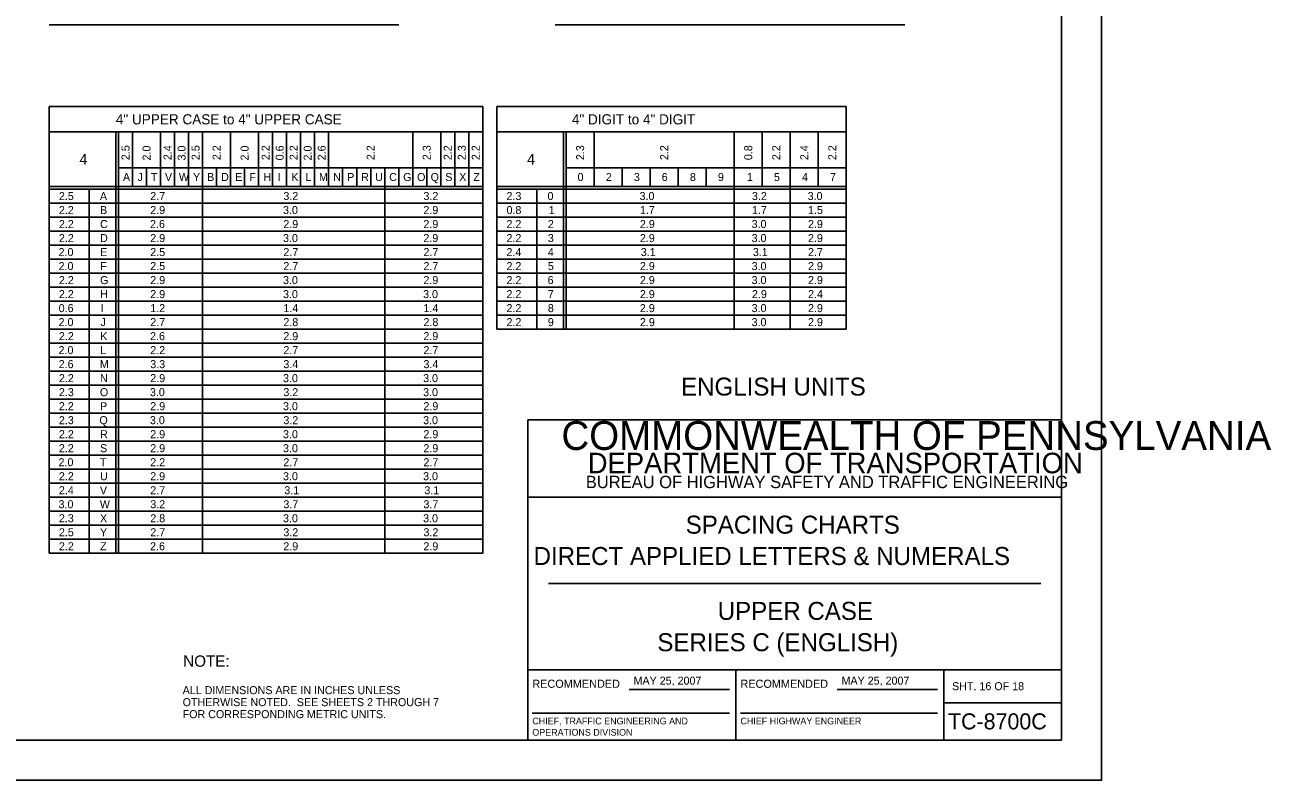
# Model space of a CAD drawing. Extents: x 637580 to 641849, y 297270 to 299646.
# Drawn here: x 640540.8 to 641007.9, y 297269.6 to 297552.6 of the extents above; entities that cross this region are included whole.
import ezdxf

# ---------------------------------------------------------------- set-up
doc = ezdxf.new("R2010")
doc.units = 0
for name, color, linetype in [('1', 7, 'Continuous'), ('2', 7, 'Continuous'), ('XCS-GRID-HVGL', 7, 'Continuous')]:
    doc.layers.add(name, color=color, linetype=linetype)

msp = doc.modelspace()

# ---------------------------------------------------------------- linework, layer by layer
at = {"layer": '1'}
for p, q in [((640929.31, 297284.63), (640929.31, 297848.63)), ((640729.31, 297284.63), (640729.31, 297404.63)), ((640729.31, 297404.63), (640929.31, 297404.63)), ((640929.31, 297375.63), (640729.31, 297375.63)), ((640737.06, 297343.31), (640921.56, 297343.31)), ((640729.31, 297311), (640929.31, 297311)), ((640807.31, 297311), (640807.31, 297284.63)), ((640885.19, 297284.63), (640885.19, 297311)), ((640767.24, 297303.57), (640804.87, 297303.57)), ((640845.24, 297303.57), (640882.87, 297303.57)), ((640885.19, 297298.63), (640929.31, 297298.63)), ((640730.99, 297294.68), (640804.87, 297294.68)), ((640808.99, 297294.68), (640882.87, 297294.68)), ((640929.31, 297284.63), (640143.31, 297284.63)), ((640143.31, 297284.63), (640729.31, 297284.63))]:
    msp.add_line(p, q, dxfattribs=at)
at = {"layer": '2'}
for p, q in [((640549.91, 297552.63), (640680.91, 297552.63)), ((640739.61, 297552.63), (640870.61, 297552.63)), ((640712.41, 297522), (640549.91, 297522)), ((640549.91, 297522), (640549.91, 297354.63)), ((640712.41, 297522), (640712.41, 297354.63)), ((640848.66, 297522), (640717.66, 297522)), ((640717.66, 297522), (640717.66, 297438.63)), ((640848.66, 297438.63), (640848.66, 297522)), ((640549.91, 297512.5), (640712.41, 297512.5)), ((640574.91, 297512.5), (640574.91, 297354.63)), ((640575.91, 297512.5), (640575.91, 297354.63)), ((640581.16, 297512.5), (640581.16, 297492.13)), ((640591.66, 297512.5), (640591.66, 297492.13)), ((640596.91, 297512.5), (640596.91, 297492.13)), ((640602.16, 297512.5), (640602.16, 297492.13)), ((640607.41, 297512.5), (640607.41, 297354.63)), ((640617.91, 297512.5), (640617.91, 297492.13)), ((640628.41, 297512.5), (640628.41, 297492.13)), ((640633.66, 297512.5), (640633.66, 297492.13)), ((640638.91, 297512.5), (640638.91, 297492.13)), ((640644.16, 297512.5), (640644.16, 297492.13)), ((640649.41, 297512.5), (640649.41, 297492.13)), ((640654.66, 297512.5), (640654.66, 297492.13)), ((640686.16, 297512.5), (640686.16, 297492.13)), ((640696.66, 297512.5), (640696.66, 297492.13)), ((640701.91, 297512.5), (640701.91, 297492.13)), ((640707.16, 297512.5), (640707.16, 297492.13)), ((640717.66, 297512.5), (640848.66, 297512.5)), ((640742.66, 297512.5), (640742.66, 297438.63)), ((640743.66, 297512.5), (640743.66, 297438.63)), ((640754.16, 297512.5), (640754.16, 297492.13)), ((640806.66, 297512.5), (640806.66, 297438.63)), ((640817.16, 297512.5), (640817.16, 297492.13)), ((640827.66, 297512.5), (640827.66, 297438.63)), ((640838.16, 297512.5), (640838.16, 297492.13)), ((640575.91, 297499.13), (640712.41, 297499.13)), ((640586.41, 297499.13), (640586.41, 297492.13)), ((640612.66, 297499.13), (640612.66, 297492.13)), ((640623.16, 297499.13), (640623.16, 297492.13)), ((640659.91, 297499.13), (640659.91, 297492.13)), ((640665.16, 297499.13), (640665.16, 297492.13)), ((640670.41, 297499.13), (640670.41, 297492.13)), ((640670.41, 297499.13), (640670.41, 297492.13)), ((640675.66, 297499.13), (640675.66, 297354.63)), ((640680.91, 297499.13), (640680.91, 297492.13)), ((640691.41, 297499.13), (640691.41, 297492.13)), ((640743.66, 297499.13), (640848.66, 297499.13)), ((640764.66, 297499.13), (640764.66, 297492.13)), ((640775.16, 297499.13), (640775.16, 297492.13)), ((640785.66, 297499.13), (640785.66, 297492.13)), ((640796.16, 297499.13), (640796.16, 297492.13)), ((640712.41, 297492.13), (640549.91, 297492.13)), ((640848.66, 297492.13), (640717.66, 297492.13)), ((640712.41, 297491.13), (640549.91, 297491.13)), ((640564.91, 297491.13), (640564.91, 297354.63)), ((640848.66, 297491.13), (640717.66, 297491.13)), ((640732.66, 297491.13), (640732.66, 297438.63)), ((640712.41, 297485.88), (640549.91, 297485.88)), ((640848.66, 297485.88), (640717.66, 297485.88)), ((640712.41, 297480.63), (640549.91, 297480.63)), ((640848.66, 297480.63), (640717.66, 297480.63)), ((640712.41, 297475.38), (640549.91, 297475.38)), ((640848.66, 297475.38), (640717.66, 297475.38)), ((640712.41, 297470.13), (640549.91, 297470.13)), ((640848.66, 297470.13), (640717.66, 297470.13)), ((640712.41, 297464.88), (640549.91, 297464.88)), ((640848.66, 297464.88), (640717.66, 297464.88)), ((640712.41, 297459.63), (640549.91, 297459.63)), ((640848.66, 297459.63), (640717.66, 297459.63)), ((640712.41, 297454.38), (640549.91, 297454.38)), ((640848.66, 297454.38), (640717.66, 297454.38)), ((640712.41, 297449.13), (640549.91, 297449.13)), ((640848.66, 297449.13), (640717.66, 297449.13)), ((640712.41, 297443.88), (640549.91, 297443.88)), ((640848.66, 297443.88), (640717.66, 297443.88)), ((640712.41, 297438.63), (640549.91, 297438.63)), ((640717.66, 297438.63), (640848.66, 297438.63)), ((640712.41, 297433.38), (640549.91, 297433.38)), ((640712.41, 297428.13), (640549.91, 297428.13)), ((640712.41, 297422.88), (640549.91, 297422.88)), ((640712.41, 297417.63), (640549.91, 297417.63)), ((640712.41, 297412.38), (640549.91, 297412.38)), ((640712.41, 297407.13), (640549.91, 297407.13)), ((640712.41, 297401.88), (640549.91, 297401.88)), ((640712.41, 297396.63), (640549.91, 297396.63)), ((640712.41, 297391.38), (640549.91, 297391.38)), ((640712.41, 297386.13), (640549.91, 297386.13)), ((640712.41, 297380.88), (640549.91, 297380.88)), ((640712.41, 297375.63), (640549.91, 297375.63)), ((640712.41, 297370.38), (640549.91, 297370.38)), ((640712.41, 297365.13), (640549.91, 297365.13)), ((640712.41, 297359.88), (640549.91, 297359.88)), ((640549.91, 297354.63), (640549.91, 297354.63)), ((640549.91, 297354.63), (640712.41, 297354.63))]:
    msp.add_line(p, q, dxfattribs=at)
at = {"layer": 'XCS-GRID-HVGL'}
msp.add_lwpolyline([(640103.31, 297863.63), (640944.31, 297863.63), (640944.31, 297269.63), (640103.31, 297269.63)], close=True, dxfattribs=at)

# ---------------------------------------------------------------- texts
at = {"layer": '1'}
for s, height, p in [('COMMONWEALTH OF PENNSYLVANIA', 10.7828, (640741.9, 297393.36)), ('DEPARTMENT OF TRANSPORTATION', 7.6837, (640751.76, 297384.61)), ('BUREAU OF HIGHWAY SAFETY AND TRAFFIC ENGINEERING', 4.6253, (640751.04, 297379.04)), ('SPACING CHARTS', 6.75, (640788.47, 297361.97)), ('DIRECT APPLIED LETTERS & NUMERALS', 6.75, (640731.47, 297350.22)), ('UPPER CASE', 6.75, (640800.47, 297329.66)), ('SERIES C (ENGLISH)', 6.75, (640777.84, 297317.91)), ('RECOMMENDED', 3.048, (640730.99, 297304.2)), ('RECOMMENDED', 3.048, (640808.99, 297304.2)), ('SHT. 16 OF 18', 3, (640888.32, 297303.31)), ('CHIEF, TRAFFIC ENGINEERING AND', 2.5, (640730.99, 297290.51)), ('CHIEF HIGHWAY ENGINEER', 2.5, (640808.99, 297290.51)), ('TC-8700C', 6, (640886.77, 297288.63)), ('OPERATIONS DIVISION', 2.5, (640730.99, 297286.26))]:
    msp.add_text(s, height=height, dxfattribs=at).set_placement(p)
at = {"layer": '2'}
for s, height, p in [('4" UPPER CASE to 4" UPPER CASE', 3.8, (640574.9, 297515.35)), ('4" DIGIT to 4" DIGIT', 3.8, (640745.81, 297515.35)), ('4', 4, (640561.28, 297500.31)), ('4', 4, (640729.03, 297500.31)), ('A', 3, (640577.56, 297494.13)), ('J', 3, (640583.04, 297494.13)), ('T', 3, (640588.04, 297494.13)), ('V', 3, (640593.31, 297494.13)), ('W', 3, (640598.53, 297494.13)), ('Y', 3, (640603.84, 297494.13)), ('B', 3, (640609.1, 297494.13)), ('D', 3, (640614.35, 297494.13)), ('E', 3, (640619.62, 297494.13)), ('F', 3, (640624.92, 297494.13)), ('H', 3, (640630.19, 297494.13)), ('I', 3, (640635.6, 297494.13)), ('K', 3, (640640.69, 297494.13)), ('L', 3, (640645.94, 297494.13)), ('M', 3, (640651.03, 297494.13)), ('N', 3, (640656.35, 297494.13)), ('P', 3, (640661.6, 297494.13)), ('R', 3, (640666.85, 297494.13)), ('U', 3, (640672.09, 297494.13)), ('C', 3, (640677.35, 297494.13)), ('G', 3, (640682.6, 297494.13)), ('O', 3, (640687.81, 297494.13)), ('Q', 3, (640692.88, 297494.13)), ('S', 3, (640698.37, 297494.13)), ('X', 3, (640703.59, 297494.13)), ('Z', 3, (640708.85, 297494.13)), ('0', 3, (640747.93, 297494.13)), ('2', 3, (640758.56, 297494.13)), ('3', 3, (640769.06, 297494.13)), ('6', 3, (640779.48, 297494.13)), ('8', 3, (640790.06, 297494.13)), ('9', 3, (640800.55, 297494.13)), ('1', 3, (640811.4, 297494.13)), ('5', 3, (640821.56, 297494.13)), ('4', 3, (640832.06, 297494.13)), ('7', 3, (640842.56, 297494.13)), ('2.5', 3, (640553.56, 297487)), ('A', 3, (640568.93, 297487)), ('2.7', 3, (640587.81, 297487)), ('3.2', 3, (640637.69, 297487)), ('3.2', 3, (640690.19, 297487)), ('2.3', 3, (640721.31, 297487)), ('0', 3, (640736.68, 297487)), ('3.0', 3, (640771.18, 297487)), ('3.2', 3, (640813.31, 297487)), ('3.0', 3, (640834.18, 297487)), ('2.2', 3, (640553.56, 297481.75)), ('B', 3, (640568.98, 297481.75)), ('2.9', 3, (640587.8, 297481.75)), ('3.0', 3, (640637.56, 297481.75)), ('2.9', 3, (640690.17, 297481.75)), ('0.8', 3, (640721.31, 297481.75)), ('1', 3, (640737.15, 297481.75)), ('1.7', 3, (640771.31, 297481.75)), ('1.7', 3, (640813.31, 297481.75)), ('1.5', 3, (640834.31, 297481.75)), ('2.2', 3, (640553.56, 297476.5)), ('C', 3, (640568.98, 297476.5)), ('2.6', 3, (640587.73, 297476.5)), ('2.9', 3, (640637.67, 297476.5)), ('2.9', 3, (640690.17, 297476.5)), ('2.2', 3, (640721.31, 297476.5)), ('2', 3, (640736.81, 297476.5)), ('2.9', 3, (640771.3, 297476.5)), ('3.0', 3, (640813.18, 297476.5)), ('2.9', 3, (640834.3, 297476.5)), ('2.2', 3, (640553.56, 297471.25)), ('D', 3, (640568.98, 297471.25)), ('2.9', 3, (640587.8, 297471.25)), ('3.0', 3, (640637.56, 297471.25)), ('2.9', 3, (640690.17, 297471.25)), ('2.2', 3, (640721.31, 297471.25)), ('3', 3, (640736.81, 297471.25)), ('2.9', 3, (640771.3, 297471.25)), ('3.0', 3, (640813.18, 297471.25)), ('2.9', 3, (640834.3, 297471.25)), ('2.0', 3, (640553.43, 297466)), ('E', 3, (640568.99, 297466)), ('2.5', 3, (640587.81, 297466)), ('2.7', 3, (640637.69, 297466)), ('2.7', 3, (640690.19, 297466)), ('2.4', 3, (640721.31, 297466)), ('4', 3, (640736.81, 297466)), ('3.1', 3, (640771.65, 297466)), ('3.1', 3, (640813.65, 297466)), ('2.7', 3, (640834.31, 297466)), ('2.0', 3, (640553.43, 297460.75)), ('F', 3, (640569.05, 297460.75)), ('2.5', 3, (640587.81, 297460.75)), ('2.7', 3, (640637.69, 297460.75)), ('2.7', 3, (640690.19, 297460.75)), ('2.2', 3, (640721.31, 297460.75)), ('5', 3, (640736.81, 297460.75)), ('2.9', 3, (640771.3, 297460.75)), ('3.0', 3, (640813.18, 297460.75)), ('2.9', 3, (640834.3, 297460.75)), ('2.2', 3, (640553.56, 297455.5)), ('G', 3, (640568.98, 297455.5)), ('2.9', 3, (640587.8, 297455.5)), ('3.0', 3, (640637.56, 297455.5)), ('2.9', 3, (640690.17, 297455.5)), ('2.2', 3, (640721.31, 297455.5)), ('6', 3, (640736.73, 297455.5)), ('2.9', 3, (640771.3, 297455.5)), ('3.0', 3, (640813.18, 297455.5)), ('2.9', 3, (640834.3, 297455.5)), ('2.2', 3, (640553.56, 297450.25)), ('H', 3, (640569.06, 297450.25)), ('2.9', 3, (640587.8, 297450.25)), ('3.0', 3, (640637.56, 297450.25)), ('3.0', 3, (640690.06, 297450.25)), ('2.2', 3, (640721.31, 297450.25)), ('7', 3, (640736.81, 297450.25)), ('2.9', 3, (640771.3, 297450.25)), ('2.9', 3, (640813.3, 297450.25)), ('2.4', 3, (640834.31, 297450.25)), ('0.6', 3, (640553.48, 297445)), ('I', 3, (640569.23, 297445)), ('1.2', 3, (640587.81, 297445)), ('1.4', 3, (640637.69, 297445)), ('1.4', 3, (640690.19, 297445)), ('2.2', 3, (640721.31, 297445)), ('8', 3, (640736.81, 297445)), ('2.9', 3, (640771.3, 297445)), ('3.0', 3, (640813.18, 297445)), ('2.9', 3, (640834.3, 297445)), ('2.0', 3, (640553.43, 297439.75)), ('J', 3, (640569.17, 297439.75)), ('2.7', 3, (640587.81, 297439.75)), ('2.8', 3, (640637.69, 297439.75)), ('2.8', 3, (640690.19, 297439.75)), ('2.2', 3, (640721.31, 297439.75)), ('9', 3, (640736.8, 297439.75)), ('2.9', 3, (640771.3, 297439.75)), ('3.0', 3, (640813.18, 297439.75)), ('2.9', 3, (640834.3, 297439.75)), ('2.2', 3, (640553.56, 297434.5)), ('K', 3, (640569.06, 297434.5)), ('2.6', 3, (640587.73, 297434.5)), ('2.9', 3, (640637.67, 297434.5)), ('2.9', 3, (640690.17, 297434.5)), ('2.0', 3, (640553.43, 297429.25)), ('L', 3, (640569.06, 297429.25)), ('2.2', 3, (640587.81, 297429.25)), ('2.7', 3, (640637.69, 297429.25)), ('2.7', 3, (640690.19, 297429.25)), ('2.6', 3, (640553.48, 297424)), ('M', 3, (640568.91, 297424)), ('3.3', 3, (640587.81, 297424)), ('3.4', 3, (640637.69, 297424)), ('3.4', 3, (640690.19, 297424)), ('2.2', 3, (640553.56, 297418.75)), ('N', 3, (640568.98, 297418.75)), ('2.9', 3, (640587.8, 297418.75)), ('3.0', 3, (640637.56, 297418.75)), ('3.0', 3, (640690.06, 297418.75)), ('ENGLISH UNITS', 6.75, (640786.74, 297413.72)), ('2.3', 3, (640553.56, 297413.5)), ('O', 3, (640568.93, 297413.5)), ('3.0', 3, (640587.68, 297413.5)), ('3.2', 3, (640637.69, 297413.5)), ('3.0', 3, (640690.06, 297413.5)), ('2.2', 3, (640553.56, 297408.25)), ('P', 3, (640568.98, 297408.25)), ('2.9', 3, (640587.8, 297408.25)), ('3.0', 3, (640637.56, 297408.25)), ('2.9', 3, (640690.17, 297408.25)), ('2.3', 3, (640553.56, 297403)), ('Q', 3, (640568.75, 297403)), ('3.0', 3, (640587.68, 297403)), ('3.2', 3, (640637.69, 297403)), ('3.0', 3, (640690.06, 297403)), ('2.2', 3, (640553.56, 297397.75)), ('R', 3, (640568.98, 297397.75)), ('2.9', 3, (640587.8, 297397.75)), ('3.0', 3, (640637.56, 297397.75)), ('2.9', 3, (640690.17, 297397.75)), ('2.2', 3, (640553.56, 297392.5)), ('S', 3, (640568.99, 297392.5)), ('2.9', 3, (640587.8, 297392.5)), ('3.0', 3, (640637.56, 297392.5)), ('2.9', 3, (640690.17, 297392.5)), ('2.0', 3, (640553.43, 297387.25)), ('T', 3, (640568.92, 297387.25)), ('2.2', 3, (640587.81, 297387.25)), ('2.7', 3, (640637.69, 297387.25)), ('2.7', 3, (640690.19, 297387.25)), ('2.2', 3, (640553.56, 297382)), ('U', 3, (640568.97, 297382)), ('2.9', 3, (640587.8, 297382)), ('3.0', 3, (640637.56, 297382)), ('3.0', 3, (640690.06, 297382)), ('2.4', 3, (640553.56, 297376.75)), ('V', 3, (640568.93, 297376.75)), ('2.7', 3, (640587.81, 297376.75)), ('3.1', 3, (640638.03, 297376.75)), ('3.1', 3, (640690.53, 297376.75)), ('3.0', 3, (640553.43, 297371.5)), ('W', 3, (640568.91, 297371.5)), ('3.2', 3, (640587.81, 297371.5)), ('3.7', 3, (640637.69, 297371.5)), ('3.7', 3, (640690.19, 297371.5)), ('2.3', 3, (640553.56, 297366.25)), ('X', 3, (640568.97, 297366.25)), ('2.8', 3, (640587.81, 297366.25)), ('3.0', 3, (640637.56, 297366.25)), ('3.0', 3, (640690.06, 297366.25)), ('2.5', 3, (640553.56, 297361)), ('Y', 3, (640568.97, 297361)), ('2.7', 3, (640587.81, 297361)), ('3.2', 3, (640637.69, 297361)), ('3.2', 3, (640690.19, 297361)), ('2.2', 3, (640553.56, 297355.75)), ('Z', 3, (640568.98, 297355.75)), ('2.6', 3, (640587.73, 297355.75)), ('2.9', 3, (640637.67, 297355.75)), ('2.9', 3, (640690.17, 297355.75)), ('NOTE:', 4.25, (640600.16, 297312.1)), ('ALL DIMENSIONS ARE IN INCHES UNLESS', 3, (640599.94, 297301.83)), ('MAY 25, 2007', 3, (640768.93, 297305.39)), ('OTHERWISE NOTED.  SEE SHEETS 2 THROUGH 7', 3, (640599.94, 297297.33)), ('FOR CORRESPONDING METRIC UNITS.', 3, (640599.94, 297292.83))]:
    msp.add_text(s, height=height, dxfattribs=at).set_placement(p)
for s, rotation, p in [('2.5', 90, (640580.04, 297501.96)), ('2.0', 90, (640587.91, 297501.83)), ('2.4', 90, (640595.79, 297501.96)), ('3.0', 90, (640601.04, 297501.83)), ('2.5', 90, (640606.29, 297501.96)), ('2.2', 90, (640614.16, 297501.96)), ('2.0', 90, (640624.66, 297501.83)), ('2.2', 90, (640632.54, 297501.96)), ('0.6', 90, (640637.79, 297501.88)), ('2.2', 90, (640643.04, 297501.96)), ('2.0', 90, (640648.29, 297501.83)), ('2.6', 90, (640653.54, 297501.88)), ('2.2', 90, (640671.91, 297501.96)), ('2.3', 90, (640692.91, 297501.96)), ('2.2', 90, (640700.79, 297501.96)), ('2.3', 90, (640706.04, 297501.96)), ('2.2', 90, (640711.29, 297501.96)), ('2.3', 90, (640750.41, 297501.96)), ('2.2', 90, (640781.91, 297501.96)), ('0.8', 90, (640813.41, 297501.96)), ('2.2', 90, (640823.91, 297501.96)), ('2.4', 90, (640834.41, 297501.96)), ('2.2', 90, (640844.91, 297501.96)), ('MAY 25, 2007', 360, (640846.88, 297305.39))]:
    msp.add_text(s, height=3, rotation=rotation, dxfattribs=at).set_placement(p)

doc.saveas('drawing.dxf')
